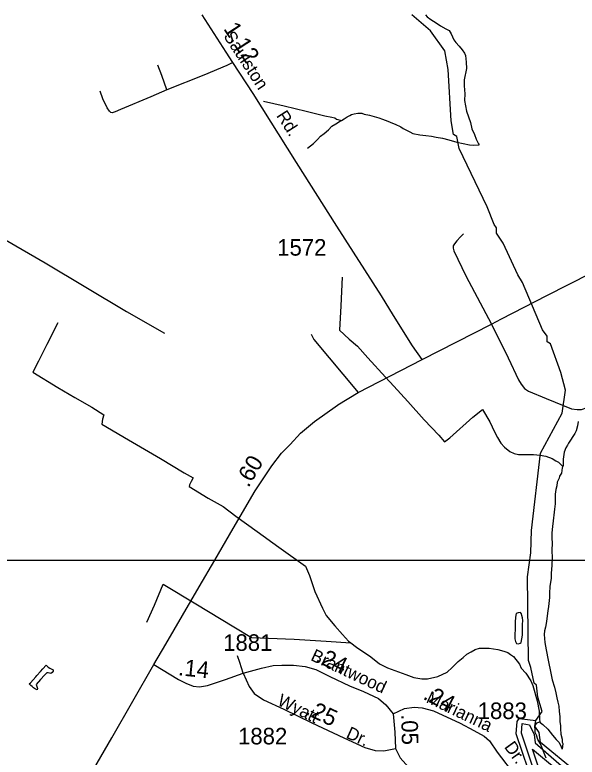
# Model space of a CAD drawing. Extents: x 2315291 to 2336543, y 597177 to 615230.
# Drawn here: x 2329008 to 2333257, y 609266 to 614871 of the extents above; entities that cross this region are included whole.
import ezdxf

# ---------------------------------------------------------------- set-up
doc = ezdxf.new("R2010")
doc.units = 0
for name, color, linetype in [('Exist Hydrographic Buffer Line', 7, 'Continuous'), ('Exist Hydrographic Creek Single Shore', 7, 'Continuous'), ('Exist Hydrographic Lake Shore', 7, 'Continuous'), ('Exist Hydrographic Misc Water Feature', 7, 'Continuous'), ('Exist Road Non-System Type 51', 7, 'Continuous'), ('Exist Road Primary US Attributed', 7, 'Continuous'), ('Exist Road Primary US Mileage Tenths English Label', 7, 'Continuous'), ('Exist Road Secondary Mileage Hundredths English Label', 7, 'Continuous'), ('Exist Road Secondary Type 51 Attributed', 7, 'Continuous'), ('Exist Road Secondary Type 51 Label', 7, 'Continuous'), ('Exist Road Secondary Type 51 Number Label', 7, 'Continuous'), ('Map Preparation Inset Cut Line', 7, 'Continuous')]:
    doc.layers.add(name, color=color, linetype=linetype)

msp = doc.modelspace()

# ---------------------------------------------------------------- linework, layer by layer
at = {"layer": 'Exist Hydrographic Buffer Line'}
for points in [[(2332973.1, 609038.8), (2332835.9, 609447.4), (2332841.5, 609520.2), (2332897.2, 609508.7), (2332931.9, 609437.8), (2332939.7, 609372.8), (2333218.3, 609128.4)], [(2333012.9, 609043.1), (2332918.8, 609326.2), (2333188.2, 609101.3)]]:
    msp.add_lwpolyline(points, dxfattribs=at)
at = {"layer": 'Exist Hydrographic Creek Single Shore'}
msp.add_lwpolyline([(2332944.4, 609543.5), (2332993.4, 609611.1), (2332958.3, 609718.1), (2332949.5, 609809.5), (2332932.5, 609825.3), (2332906.5, 609942.3), (2332889.4, 609994.2), (2332882.5, 610627.3), (2332905.4, 610808.7), (2332912.4, 610976.3), (2332980.5, 611559.9), (2333144.3, 611861.9), (2333167.5, 612036.7), (2333132.4, 612169.9), (2333055.3, 612386.7), (2333030.5, 612402.1), (2333029.5, 612444.7), (2332995.5, 612492.6), (2332842.5, 612850.6), (2332808.4, 612908.3), (2332697.3, 613146.6), (2332646.5, 613223.3), (2332646.5, 613262.7), (2332629.4, 613288.3), (2332577.4, 613420.8), (2332364.3, 613861.7), (2332347.5, 613952.9), (2332322.5, 613968.3), (2332304.4, 614069.3), (2332283.3, 614459), (2332256.4, 614599.1), (2332147.4, 614748.9), (2332007.9, 614870.5)], dxfattribs=at)
at = {"layer": 'Exist Hydrographic Lake Shore'}
for points in [[(2333467.8, 606503.8), (2333234.5, 606572.2), (2332924.5, 606694.2), (2332899.5, 606745.7), (2332905.4, 606952.7), (2332929.4, 606996.3), (2332962.4, 607079.7), (2333092.4, 607337.6), (2333132.4, 607486.9), (2333113.4, 607722.4), (2333079.5, 607845.8), (2333059.4, 608110.8), (2333006.5, 608354.8), (2332984.4, 608878.9), (2332942.3, 608952.7), (2332933.5, 609034.4), (2332795.5, 609442.3), (2332802.5, 609534.5), (2332819.5, 609558.1), (2332944.4, 609543.5)], [(2333248.5, 609155.4), (2332979.5, 609377.5), (2332970.4, 609452.7), (2332936.4, 609500.6), (2332944.4, 609543.5)]]:
    msp.add_lwpolyline(points, dxfattribs=at)
at = {"layer": 'Exist Hydrographic Misc Water Feature'}
for points in [[(2332111.3, 614870.5), (2332124.2, 614856.3), (2332150.6, 614836.5), (2332190.8, 614809), (2332224.9, 614787.2), (2332263.4, 614765.6), (2332289.7, 614751.9), (2332305.9, 614726.4), (2332323.9, 614682.7), (2332340.3, 614662.8), (2332364.5, 614632.8), (2332388.9, 614605.2), (2332405.3, 614581.2), (2332413.3, 614563.4), (2332417.8, 614513.7), (2332420.5, 614465.8), (2332403.7, 614379.5), (2332404.1, 614333.6), (2332406.8, 614273.6), (2332405.3, 614223.6), (2332421.7, 614144), (2332450.8, 614058.1), (2332461.5, 614010.3), (2332479.8, 613966.6), (2332494.1, 613932.8), (2332512.4, 613896.8), (2332516.7, 613888.9)], [(2330886.1, 614219.4), (2331044, 614183), (2331208.6, 614142.8), (2331350.7, 614108.5), (2331402.8, 614097), (2331424.8, 614093.3), (2331439.3, 614083.4), (2331475, 614073.6)], [(2331475, 614073.6), (2331495.1, 614086), (2331519.1, 614100.2), (2331539, 614110.2), (2331552.7, 614118.6), (2331572.4, 614122.6), (2331598.6, 614129.2), (2331628.6, 614127.1), (2331646.6, 614121.6), (2331688.9, 614112), (2331757.1, 614092.7), (2331784.8, 614082.9), (2331825, 614067.5), (2331861.1, 614053.6), (2331881.6, 614044), (2331923.2, 614024.4), (2331941.7, 614012.7), (2331991.9, 613987.2), (2332015.9, 613975.6), (2332068, 613964.1), (2332114.3, 613958.7), (2332156.2, 613955.3), (2332190.2, 613947.3), (2332238.2, 613940.1), (2332286.6, 613926.3), (2332348.7, 613909.2), (2332442.4, 613890.3), (2332472.4, 613886.6), (2332516.7, 613888.9)], [(2331219.7, 613865), (2331241.6, 613881.2), (2331263.4, 613899.4), (2331294.8, 613929.9), (2331318.3, 613954), (2331344.2, 613974.4), (2331377.8, 614002.6), (2331403.4, 614028.8), (2331433.4, 614047.4), (2331461.5, 614065.5), (2331475, 614073.6)], [(2331480.1, 612890.2), (2331470.1, 612674.4), (2331461.9, 612490.3), (2331535.1, 612421.3), (2331597.6, 612367.7), (2331674.5, 612280.7), (2331808.2, 612134), (2331872.6, 612066.7), (2331977.8, 611950), (2332101.2, 611813.3), (2332212.4, 611696.9), (2332255, 611647), (2332294.4, 611677.6), (2332468.7, 611833.5), (2332540.2, 611890.1)], [(2329332.6, 612545.4), (2329250.8, 612380.6), (2329185.8, 612256.1), (2329145, 612171.4), (2329333.8, 612057.8), (2329462.6, 611981.2), (2329589.5, 611908.2), (2329681.6, 611851.4), (2329670.3, 611817.4), (2329665, 611779.2), (2329867.6, 611661.5), (2330109.3, 611520.2), (2330286.3, 611412), (2330356.6, 611375), (2330339.2, 611346.8), (2330327.3, 611320.7), (2330325.3, 611308.8), (2330468.2, 611220.4), (2330581, 611157.6), (2330677.8, 611084.6), (2330838.9, 610970.4), (2331001.9, 610852.2), (2331203.3, 610708.3)], [(2332540.2, 611890.1), (2332597.2, 611798.7), (2332631.9, 611721.3), (2332654.3, 611679.4), (2332678.9, 611637.7), (2332707.2, 611606.2), (2332747.3, 611574.6), (2332781.8, 611558.9), (2332813.6, 611551.2), (2332889.7, 611550.4), (2332927.4, 611550.4), (2332977.6, 611545.2), (2333019.4, 611539.3), (2333068, 611521.9), (2333096.1, 611504.3), (2333116.2, 611492.7), (2333148.4, 611461.2)], [(2333264.7, 611800.1), (2333258.9, 611768.1), (2333249.7, 611729.8), (2333237.8, 611709.7), (2333224.1, 611685.8), (2333206, 611659.3), (2333190.5, 611635.2), (2333182.7, 611621), (2333171, 611601.3), (2333157.4, 611568.9), (2333155.2, 611550.9), (2333150.1, 611516.8), (2333150.3, 611494.9), (2333150.3, 611482.7), (2333150.7, 611466.9), (2333148.4, 611461.2)], [(2333148.4, 611461.2), (2333144.5, 611450.8), (2333137.1, 611410.9), (2333123.2, 611386.7), (2333121.4, 611372.7), (2333105.8, 611342.6), (2333101.9, 611314.4), (2333094.7, 611286.3), (2333090.8, 611252.5), (2333089.4, 611218.6), (2333089.4, 611178.4), (2333085.9, 611138.4), (2333082.2, 611116.3), (2333075, 611050.4), (2333069.7, 611008.3), (2333066, 610960.1), (2333066.4, 610914.2), (2333066.8, 610886.2), (2333065.6, 610822.3), (2333067.8, 610772.5), (2333064.4, 610716.2), (2333059.4, 610652.5), (2333059.6, 610616.3), (2333050.2, 610554.1), (2333048.8, 610504.4), (2333047.3, 610470.2), (2333039.7, 610402.4), (2333036.1, 610370.1), (2333030.7, 610332.4), (2333025, 610290.3), (2333017.6, 610246), (2333009.8, 610219.9), (2333008.2, 610192.2), (2333012.7, 610131.9), (2333021.7, 610076.2), (2333036.5, 609998.6), (2333057, 609900.6), (2333068, 609848.6), (2333086.3, 609793.2), (2333095.1, 609751.3), (2333103.3, 609713.2), (2333111.5, 609681.5), (2333118.1, 609651.3), (2333120.3, 609609.6), (2333126.7, 609573.8), (2333126.9, 609533.6), (2333129.6, 609505.6), (2333131.6, 609479.8), (2333134.3, 609438), (2333142.9, 609401.8), (2333142.9, 609379.9), (2333149, 609368), (2333143.3, 609326)], [(2331203.3, 610708.3), (2331233.9, 610636.8), (2331275.7, 610515.3), (2331333.1, 610389.9), (2331361.2, 610334.2), (2331426.2, 610257.1), (2331482.8, 610191.8), (2331529.5, 610140.2), (2331545.9, 610128.4)], [(2330006.4, 610283.8), (2330063, 610412.3), (2330129.9, 610570.9), (2330376.9, 610423.5), (2330662.6, 610250.7), (2330795.5, 610168.3), (2331119.4, 610155.6), (2331361.6, 610142.3), (2331545.9, 610128.4)], [(2332843.7, 610250.2), (2332843.7, 610268.1), (2332844.9, 610296.3), (2332843.1, 610318), (2332838.6, 610334.1), (2332834.9, 610348.1), (2332828.3, 610358), (2332810.7, 610355.8), (2332794.7, 610349.6), (2332790.8, 610323.8), (2332789.2, 610285.6), (2332787.7, 610223.8), (2332785.9, 610199.7), (2332784.7, 610173.5), (2332786.7, 610157.8), (2332790.8, 610139.8), (2332797.2, 610123.8), (2332813, 610121.8), (2332826.9, 610126.2), (2332832.9, 610132.2), (2332838.6, 610158.1), (2332842.5, 610186.4), (2332843.9, 610218.1), (2332843.7, 610250.2)], [(2331545.9, 610128.4), (2331590, 610094.9), (2331698.7, 610022.3), (2331763.1, 609970.7), (2331823.4, 609939.4), (2331962, 609888.9), (2332023.9, 609867.9), (2332082, 609856.3), (2332126.2, 609856.9), (2332204, 609873.6), (2332273.7, 609908.1), (2332313, 609942.7), (2332358.8, 609987), (2332394.4, 610017.7), (2332423.8, 610043.7), (2332456, 610060.3), (2332485.7, 610078.6), (2332519.3, 610089), (2332591.3, 610087.5), (2332657.3, 610078.3), (2332701.8, 610066.8), (2332733.4, 610055.1), (2332752.1, 610041.4), (2332776.1, 610025.6), (2332821, 609968.1), (2332834.7, 609938.5), (2332869.4, 609900.9), (2332906.1, 609843), (2332922.5, 609807.3), (2332953.4, 609691.9), (2332968.6, 609613.8), (2332972.9, 609547.9), (2332977.2, 609528.1)], [(2329201.2, 609911.4), (2329219, 609931.4), (2329244.4, 609959.6), (2329260.4, 609945.8), (2329272.7, 609937.9), (2329286.7, 609930.1), (2329296.9, 609924.6), (2329296.9, 609914.4), (2329289.1, 609904.2), (2329280.9, 609898.2), (2329261.3, 609901.9), (2329249.2, 609901.7), (2329231.3, 609885.7), (2329201.8, 609851.2), (2329168.2, 609815), (2329174.3, 609799), (2329180.7, 609783.1), (2329176.8, 609775.1), (2329164.7, 609779), (2329150.1, 609788.9), (2329138.6, 609798.7), (2329130.2, 609806.5), (2329115.9, 609818.3), (2329126.3, 609826.5), (2329167.5, 609873), (2329175.1, 609883.2), (2329201.2, 609911.4)], [(2333022.1, 609258.6), (2332978.8, 609366.1), (2332960.6, 609400.1), (2332948.5, 609431.9), (2332940.3, 609451.8), (2332940.1, 609475.7), (2332937.4, 609495.6), (2332941.5, 609509.6), (2332953.4, 609525.6), (2332971.1, 609531.9), (2332977.2, 609528.1)], [(2332977.2, 609528.1), (2332997.5, 609512.1), (2333035.9, 609476.7), (2333069.9, 609431), (2333098.6, 609399.6), (2333118.7, 609379.5), (2333128.9, 609361.8), (2333143.3, 609326)]]:
    msp.add_lwpolyline(points, dxfattribs=at)
at = {"layer": 'Exist Road Non-System Type 51'}
for points in [[(2330157.6, 614305.2), (2330119.2, 614413.6), (2330087.5, 614490.3)], [(2330655.6, 614511), (2330609.3, 614487), (2330436, 614415.3), (2330157.6, 614305.2)], [(2330157.6, 614305.2), (2330035.9, 614251.8), (2329807.5, 614155), (2329767.5, 614138.4), (2329744.1, 614131.7), (2329734.1, 614133.3), (2329722.4, 614143.4), (2329705.8, 614168.4), (2329672.4, 614236.8), (2329652.4, 614293.5)], [(2328176.3, 612983.1), (2328378.9, 613313.4), (2328453.9, 613448.5), (2328588.9, 613373.5), (2329237.8, 612998.1), (2329853, 612630.3), (2330138.1, 612467)], [(2332397.6, 613218.1), (2332375.7, 613194), (2332348.1, 613163.7), (2332330.2, 613141.6), (2332320.5, 613125.4), (2332318.7, 613109.3), (2332324.8, 613087.5), (2332414.8, 612900.5), (2332609.9, 612536.1)], [(2332609.9, 612536.1), (2332734.9, 612281.7), (2332813.3, 612114.9), (2332833.3, 612083.2), (2332858.3, 612049.8), (2332889.9, 612029.8), (2333023.3, 611973.1), (2333213.4, 611896.3), (2333256.7, 611889.7), (2333290.1, 611891.3), (2333331.7, 611904.7), (2333368.4, 611914.7), (2333401.8, 611913), (2333430.1, 611906.4), (2333476.8, 611876.3), (2333608.5, 611772.9), (2333670.2, 611721.2), (2333693.5, 611687.8), (2333710.2, 611657.8), (2333723.5, 611617.8), (2333728.5, 611584.4), (2333747.6, 611469.5), (2333830.2, 610943.8), (2333859.1, 610753.3)], [(2331247.8, 612460.2), (2331267.9, 612418.5), (2331601.3, 612018.1)], [(2330732.7, 609899.6), (2330707.7, 609979.6), (2330689.4, 610029.7)]]:
    msp.add_lwpolyline(points, dxfattribs=at)
at = {"layer": 'Exist Road Primary US Attributed'}
for points in [[(2332686, 612575.2), (2333028.3, 612751.3), (2334035.3, 613262.6), (2335155.6, 613832.5), (2336050.3, 614283.7)], [(2332084.7, 612268.3), (2332609.9, 612536.1), (2332686, 612575.2)], [(2331449.4, 611925), (2331601.3, 612018.1), (2332084.7, 612268.3)], [(2330059.2, 609966.3), (2330149.2, 610118.1), (2330401, 610551.8), (2330518.4, 610753.3), (2330657.7, 610992.2), (2330822.7, 611275.8), (2330949.4, 611466), (2331022.8, 611561.1), (2331089.5, 611626.1), (2331166.2, 611712.9), (2331271.2, 611799.6), (2331446.2, 611923), (2331449.4, 611925)], [(2329182.5, 608446.1), (2329277.3, 608610.1), (2329740.8, 609411.6), (2330059.2, 609966.3)]]:
    msp.add_lwpolyline(points, dxfattribs=at)
at = {"layer": 'Exist Road Secondary Type 51 Attributed'}
for points in [[(2331869.9, 612600.9), (2331778.8, 612747.8), (2331441.2, 613275.9), (2331136.2, 613756.3), (2330807.7, 614277.6), (2330655.6, 614511), (2330604.3, 614589.6), (2330424.3, 614870.5)], [(2332084.7, 612268.3), (2332012.8, 612370.5), (2331869.9, 612600.9)], [(2330059.2, 609966.3), (2330244.2, 609852.9), (2330299.3, 609824.5), (2330354.3, 609801.1), (2330402.6, 609796.1), (2330462.6, 609806.1), (2330601, 609851.2), (2330732.7, 609899.6)], [(2330732.7, 609899.6), (2330871.1, 609937.9), (2330959.4, 609958), (2331024.5, 609959.6), (2331112.8, 609959.6), (2331201.2, 609951.3), (2331281.2, 609927.9), (2331389.2, 609874.5), (2331535.9, 609805.1), (2331643, 609761.9), (2331756.3, 609708.6), (2331811.3, 609661.9), (2331866.3, 609593.5)], [(2330732.7, 609899.6), (2330779.4, 609799.5), (2330816.1, 609745.3), (2330887.8, 609698.6), (2331039.5, 609626.8), (2331251.2, 609525.1), (2331492.9, 609411.6), (2331653, 609338.2), (2331729.6, 609316.5), (2331796.3, 609313.2), (2331834.7, 609321.5), (2331883, 609329.9)], [(2331866.3, 609593.5), (2331953, 609631.8), (2332024.7, 609643.5), (2332084.7, 609638.5), (2332171.4, 609615.1), (2332373.1, 609521.7), (2332476.5, 609466.7), (2332554.9, 609423.3), (2332594.9, 609389.9), (2332653.2, 609304), (2332791.6, 609121.4), (2332860.2, 609025.7), (2332874.9, 609006.3)], [(2331866.3, 609593.5), (2331879.7, 609453.3), (2331883, 609329.9)], [(2331883, 609329.9), (2331919.7, 609259.8), (2331984.7, 609188.1), (2332106.4, 609124.7), (2332313.1, 609031.3), (2332564.9, 608912.8), (2332631.5, 608902.8), (2332688.2, 608906.2), (2332748.2, 608924.5), (2332793.3, 608952.9), (2332874.9, 609006.3)]]:
    msp.add_lwpolyline(points, dxfattribs=at)
at = {"layer": 'Map Preparation Inset Cut Line'}
for p, q in [((2322567.3, 610753.3), (2330518.4, 610753.3)), ((2330518.4, 610753.3), (2333859.1, 610753.3))]:
    msp.add_line(p, q, dxfattribs=at)

# ---------------------------------------------------------------- texts
at = {"layer": 'Exist Road Primary US Mileage Tenths English Label'}
msp.add_text('.60', height=125, rotation=59.7016, dxfattribs=at).set_placement((2330773, 611295.8))
at = {"layer": 'Exist Road Secondary Mileage Hundredths English Label'}
for s, rotation, p in [('1.12', 303.2363, (2330581, 614765.8)), ('.24', 334.6585, (2331273, 609990.1)), ('.14', 354.2133, (2330238.4, 609884.6)), ('.24', 332.7335, (2332085.7, 609708)), ('.25', 334.9573, (2331196.2, 609592.2)), ('.05', 271.491, (2331926.7, 609589))]:
    msp.add_text(s, height=125, rotation=rotation, dxfattribs=at).set_placement(p)
at = {"layer": 'Exist Road Secondary Type 51 Label'}
for s, rotation, p in [('Saulston', 303.2363, (2330581, 614709.4)), ('Rd.', 302.6652, (2330980.7, 614110)), ('Brantwood', 335.0603, (2331236.7, 610000.1)), ('Marianna', 334.4971, (2332109.1, 609682.6)), ('Wyatt', 333.9021, (2330984.4, 609662.9)), ('Dr.', 335.6555, (2331504.1, 609414)), ('Dr.', 305.898, (2332701.8, 609342.3))]:
    msp.add_text(s, height=95, rotation=rotation, dxfattribs=at).set_placement(p)
at = {"layer": 'Exist Road Secondary Type 51 Number Label'}
for s, p in [('1572', (2330990.4, 613052.3)), ('1881', (2330582.2, 610068.1)), ('1883', (2332505.1, 609553.4)), ('1882', (2330694.6, 609362.1))]:
    msp.add_text(s, height=125, dxfattribs=at).set_placement(p)

doc.saveas('drawing.dxf')
